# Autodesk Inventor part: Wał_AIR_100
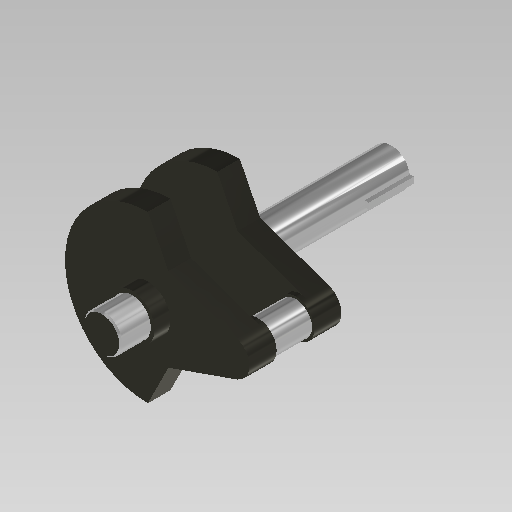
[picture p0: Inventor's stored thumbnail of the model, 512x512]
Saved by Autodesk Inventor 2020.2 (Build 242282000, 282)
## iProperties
Created: 2014-10
Part Number: Wał_AIR_100
Material: Ogólny
Document SubType Name: Modeling
Designer: F.Stasiak
Density: 1 g/cm^3
Appearance: Brąz armatni
Catalog Web Link: www.expertbooks.pl
Manager: www.cadconsulting.pl
Company: Fabian Stasiak CAD Consulting
Author: F.Stasiak
Subject: Zbiór ćwiczeń. Autodesk Inventor 2020. Kurs Professional
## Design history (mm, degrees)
sketch "Szkic1"
  geometry: C1 r 12.5 at (0, 0); 1 further point
  constraints: 1 centre point, 1 coincident
  dimensions: "d0" = 25 diameter of C1
extrude "Wyciągnięcie proste1" new body sketch "Szkic1" distance "d1" = 90; taper "d2" = 0 deg
sketch "Szkic2"
  geometry: C1 r 15 at (0, 0); 1 further point
  constraints: 1 centre point, 1 coincident
  dimensions: "d3" = 30 diameter of C1
extrude "Wyciągnięcie proste2" join sketch "Szkic2" distance "d4" = 10.5; taper "d5" = 0 deg
sketch "Szkic3"
  geometry: L1 (0, -55)-(13.591, -27.753); L2 (0, 55)-(13.591, 27.753); L3 (55, 0)-(0, 0); L4 (13.591, -27.753)-(59.133, -11.797); L5 (13.591, 27.753)-(59.133, 11.797); A1 r 55 centre (0, 0) between (0, 55) and (0, -55); A2 r 12.5 centre (55, 0) between (59.133, -11.797) and (59.133, 11.797); 1 further point
  constraints: 10 end point, 4 point on circle, 2 centre point, 2 tangent, 1 coincident, 1 horizontal, 2 other
  dimensions: "d6" = 110 diameter of A1; "d7" = 25 diameter of A2
extrude "Wyciągnięcie proste3" join sketch "Szkic3" distance "d8" = 15; taper "d9" = 0 deg
sketch "Szkic5"
  geometry: A1 r 12.5 centre (55, 0) between (59.133, -11.797) and (59.133, 11.797) reference; 2 further points
  constraints: 1 coincident, 3 other
extrude "Wyciągnięcie proste5" join sketch "Szkic5" distance "d14" = 3; taper "d15" = 0 deg
sketch "Szkic6"
  geometry: C1 r 12.5 at (0, 0) reference; C2 r 11 at (0, 0); 1 further point
  constraints: 1 centre point, 1 coincident
  dimensions: "d16" = 22 diameter of C2
extrude "Wyciągnięcie proste6" join sketch "Szkic6" distance "d17" = 25; taper "d18" = 0 deg
sketch "Szkic7"
  geometry: C1 r 12.5 at (0, 0) reference; 1 further point
extrude "Wyciągnięcie proste7" join sketch "Szkic7" distance "d19" = 3; taper "d20" = 0 deg
sketch "Szkic8"
  geometry: L1 (4.133, 11.797)-(-41.409, 27.753) reference; L2 (-41.409, 27.753)-(-55, 55) reference; L3 (-55, -55)-(-41.409, -27.753) reference; L4 (-41.409, -27.753)-(4.133, -11.797) reference; A1 r 12.5 centre (0, 0) between (4.133, 11.797) and (4.133, -11.797) reference; A2 r 55 centre (-55, 0) between (-55, 55) and (-55, -55) reference; A3 r 12.5 centre (0, 0) between (4.133, -11.797) and (4.133, 11.797) reference; 1 further point
extrude "Wyciągnięcie proste8" join sketch "Szkic8" distance "d21" = 15; taper "d22" = 0 deg
sketch "Szkic9"
  geometry: C1 r 15 at (-55, 0) reference; 1 further point
extrude "Wyciągnięcie proste9" join sketch "Szkic9" distance "d23" = 10.5; taper "d24" = 0 deg
sketch "Szkic10"
  geometry: C1 r 12.5 at (0, 0); 1 further point
  constraints: 1 centre point, 1 coincident
  dimensions: "d25" = 25 diameter of C1
extrude "Wyciągnięcie proste10" join sketch "Szkic10" distance "d26" = 20; taper "d27" = 0 deg
chamfer "Faza1" distance "d28" = 1; stored, may be unused: second distance "d29" = 2, angle "d30" = 45 deg
sketch "Szkic11"
  geometry: L1 (-12.339, -2)-(-15, -2); L2 (-15, -2)-(-15, 2); L3 (-15, 2)-(-12.339, 2); L4 (0, 0)-(-15, 0); A1 r 12.5 centre (0, 0) between (-12.339, 2) and (-12.339, -2); 2 further points
  constraints: 8 end point, 2 horizontal, 2 perpendicular, 2 point on circle, 1 centre point, 1 midpoint, 4 other
  dimensions: "d31" = 15 distance from line of L2 point (0, 0); "d32" = 4 distance of L1.end L2.end
extrude "Wyciągnięcie proste11" join sketch "Szkic11" distance "d33" = 30; taper "d34" = 0 deg
node "Bryła1"
node "Pętla rzutowana1"
node "Pętla rzutowana2"
